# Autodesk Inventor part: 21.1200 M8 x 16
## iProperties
Created: 2006-02
Part Number: 21.1200 M8 x 16
Material: Steel, Mild
Description: Cylinder Head Cap Screw
Document SubType Name: Modeling
Standard: DIN 7984
Designer: Andy Moles
Standards Organization: DIN
Language: en-US
Size Designation: M8 x 16
Categories: <MemberInstance><Categories><Category DisplayName="Fasteners" InternalName="e4da775c-781d-43d5-af7c-5136215cf5a6" Mnemonic="FSTN"><Category DisplayName="Bolts"
Density: 7.86 g/cm^3
Mass: 10.6827 g
Surface Area: 9.17139 cm^2
Volume: 1.35912 cm^3
Author: Andy Moles
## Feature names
1. Body [Revolution]
2. Slot [Extrusion]
3. Fillet1
4. Chamfer1
